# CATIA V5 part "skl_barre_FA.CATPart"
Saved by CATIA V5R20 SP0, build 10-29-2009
Part number: skl_barre_FA
Publications: "Droite_FA", "Axe_pivot_FA_F", "Axe_pivot_FA_A"
Bounding box of the stored display mesh (mm): x 0 to 5, y -86 to 6, z -6 to 56
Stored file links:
  D:\Dropbox\IAO_2012\IAO_2012_742_prousseau\skl_barre_FA.CATPart
  D:\Dropbox\IAO_2012\IAO_2012_742_prousseau\skl_barre_EF.CATPart
  D:\Dropbox\IAO_2012\IAO_2012_742_prousseau\skl_IAO.CATProduct
  D:\Dropbox\IAO_2012\IAO_2012_742_prousseau\skl_barre_AB.CATPart
  D:\Dropbox\IAO_2012\IAO_2012_742_prousseau\skl_barre_BC.CATPart
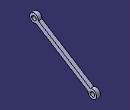
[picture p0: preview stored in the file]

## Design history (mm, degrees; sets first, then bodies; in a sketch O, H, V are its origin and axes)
Set1
  Point1 "Point_A": linked copy from another document
  Point2 "Point_F": linked copy from another document
Set2
  Line1 "Droite_FA": type PtPt, FirstPoint Point3, SecondPoint Point4
  Point3 "Point_F": stored without definition
  Point4 "Point_A": stored without definition
  Line2 "Axe_pivot_FA_F": type Normal, RefPoint Point3, RefSkin Plane1, Start -20, End 20
  Plane1 "Plan_Ref": stored without definition
  Line3 "Axe_pivot_FA_A": type Normal, RefPoint Point4, RefSkin Plane2, Start -20, End 20
  Plane2 "Plan_Ref": stored without definition
  Point5 "Point_C": stored without definition
Body1 (main body)
  Sketch1 on yz-plane, origin (0, 0, 0), H (0, 1, 0), V (0, 0, 1)
    line L1 (-74.0037, 49.79) -> (-2.8163, 5.298)
    line L2 (-5.9963, 0.21) -> (-77.1837, 44.702)
    reference projected line E1 (0, 0) -> (-80, 50) from Line1
    reference projected line E2 (0, 0) -> (-80, 50) from Line1
    arc A1 centre (0, 0) radius 6 from (-5.9963, 0.21) to (-2.8163, 5.298) ccw
    point P1 (0, 0)
    circle A2 centre (0, 0) radius 3
    point P2 (0, 0)
    arc A3 centre (-80, 50) radius 6 from (-74.0037, 49.79) to (-77.1837, 44.702) ccw
    point P3 (-80, 50)
    circle A4 centre (-80, 50) radius 3
    point P4 (-80, 50)
    reference projected point E3 (-80, 50) from Point1
    reference projected point E4 (-80, 50) from Point1
    reference projected point E5 (0, 0) from Point2
    reference projected point E6 (0, 0) from Point2
    distance L2 L1 = 6
    radius A4 = 3
    radius A3 = 6
    radius A2 = 3
    radius A1 = 6
    parallelism: L1 E1
    symmetry: L2 L1 E2
    coincidence: E3 P4, P3 E4, E5 P2, P1 E6
  Pad1: profile Sketch1, direction (1, 0, 0), length 5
